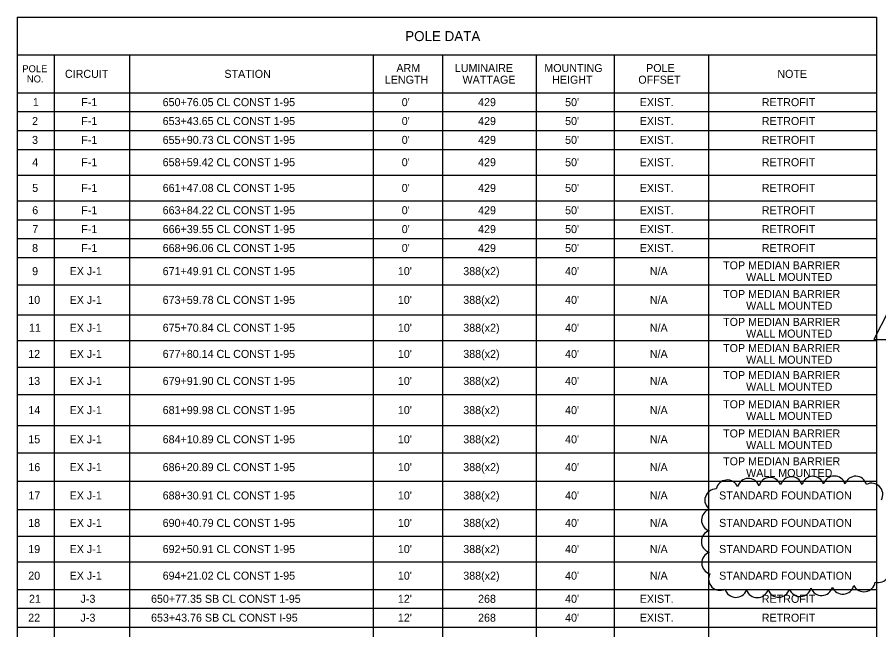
# Model space of a CAD drawing. Extents: x -838.2 to -802.1, y -2200.5 to -2187.7.
# Drawn here: x -817.54 to -810, y -2193.08 to -2187.72 of the extents above; entities that cross this region are included whole.
import ezdxf

# ---------------------------------------------------------------- set-up
doc = ezdxf.new("R2010")
doc.units = 0
for name, color, linetype in [('Cloud_dp', 7, 'Continuous'), ('SumBoxBorder_dp', 7, 'Continuous'), ('SumBoxLines_dp', 7, 'Continuous'), ('SumBoxLinesMin_dp', 7, 'Continuous'), ('TextLabel', 7, 'Continuous')]:
    doc.layers.add(name, color=color, linetype=linetype)

msp = doc.modelspace()

# ---------------------------------------------------------------- linework, layer by layer
at = {"layer": 'Cloud_dp'}
msp.add_lwpolyline([(-809.9202, -2190.2923), (-810.047, -2190.5364), (-809.7935, -2190.5364)], close=True, dxfattribs=at)
for centre, radius, start, end in [((-810.5792, -2191.8323), 0.0985, 18.60955, 163.60955), ((-810.3916, -2191.8298), 0.0985, 17.90326, 162.90326), ((-810.2046, -2191.8315), 0.0986, 16.0749, 161.0749), ((-811.3278, -2191.8641), 0.0985, 23.06971, 168.06971), ((-811.1418, -2191.8504), 0.0985, 20.37871, 165.37871), ((-810.9545, -2191.8424), 0.0985, 19.50674, 164.50674), ((-810.7669, -2191.8366), 0.0985, 19.02787, 164.02787), ((-810.066, -2191.8924), 0.0985, 331.459, 116.459), ((-811.4251, -2191.9423), 0.0985, 89.50987, 234.50987), ((-811.4542, -2192.117), 0.0985, 106.53377, 251.53377), ((-811.4555, -2192.3043), 0.0985, 107.68881, 252.68881), ((-811.4525, -2192.4915), 0.0985, 109.15664, 254.15664), ((-810.0083, -2192.5635), 0.0985, 254.40415, 39.40415), ((-811.3921, -2192.632), 0.0985, 152.35826, 297.35826), ((-810.6905, -2192.6861), 0.0985, 199.81345, 344.81345), ((-810.5031, -2192.6776), 0.0985, 200.35107, 345.35107), ((-810.3163, -2192.6658), 0.0985, 201.87855, 346.87855), ((-810.1322, -2192.644), 0.0985, 206.60481, 351.60481), ((-811.2518, -2192.6935), 0.0985, 195.25606, 340.25606), ((-811.0654, -2192.6962), 0.0985, 198.13107, 343.13107), ((-810.878, -2192.6925), 0.0985, 199.1138, 344.1138)]:
    msp.add_arc(centre, radius, start, end, dxfattribs=at)
at = {"layer": 'SumBoxBorder_dp'}
for p, q in [((-817.5362, -2187.7197), (-810.0212, -2187.7197)), ((-817.5362, -2187.7197), (-817.5362, -2197.0722)), ((-810.0212, -2187.7197), (-810.0212, -2197.0722)), ((-810.0212, -2187.7197), (-810.0212, -2197.0722)), ((-817.5362, -2188.0497), (-810.0212, -2188.0497)), ((-817.5362, -2188.0497), (-810.0212, -2188.0497))]:
    msp.add_line(p, q, dxfattribs=at)
at = {"layer": 'SumBoxLines_dp'}
for p, q in [((-817.2137, -2188.0497), (-817.2137, -2197.0722)), ((-817.2137, -2188.0497), (-817.2137, -2197.0722)), ((-816.5537, -2188.0497), (-816.5537, -2197.0722)), ((-816.5537, -2188.0497), (-816.5537, -2197.0722)), ((-814.4237, -2188.0497), (-814.4237, -2195.0322)), ((-814.4237, -2188.0497), (-814.4237, -2197.0722)), ((-813.8162, -2188.0497), (-813.8162, -2197.0722)), ((-813.8162, -2188.0497), (-813.8162, -2197.0722)), ((-812.9987, -2188.0497), (-812.9987, -2197.0722)), ((-812.9987, -2188.0497), (-812.9987, -2197.0722)), ((-812.3162, -2188.0497), (-812.3162, -2197.0722)), ((-812.3162, -2188.0497), (-812.3162, -2197.0722)), ((-811.4912, -2188.0497), (-811.4912, -2197.0722)), ((-811.4912, -2188.0497), (-811.4912, -2197.0722)), ((-817.5362, -2188.3797), (-810.0212, -2188.3797))]:
    msp.add_line(p, q, dxfattribs=at)
at = {"layer": 'SumBoxLinesMin_dp'}
for p, q in [((-817.5362, -2188.3797), (-810.0212, -2188.3797)), ((-817.5362, -2188.5447), (-810.0212, -2188.5447)), ((-817.5362, -2188.5447), (-810.0212, -2188.5447)), ((-817.5362, -2188.7097), (-810.0212, -2188.7097)), ((-817.5362, -2188.7097), (-810.0212, -2188.7097)), ((-817.5362, -2188.8747), (-810.0212, -2188.8747)), ((-817.5362, -2188.8747), (-810.0212, -2188.8747)), ((-817.5362, -2189.0997), (-810.0212, -2189.0997)), ((-817.5362, -2189.0997), (-810.0212, -2189.0997)), ((-817.5362, -2189.3247), (-810.0212, -2189.3247)), ((-817.5362, -2189.3247), (-810.0212, -2189.3247)), ((-817.5362, -2189.4897), (-810.0212, -2189.4897)), ((-817.5362, -2189.4897), (-810.0212, -2189.4897)), ((-817.5362, -2189.6547), (-810.0212, -2189.6547)), ((-817.5362, -2189.6547), (-810.0212, -2189.6547)), ((-817.5362, -2189.8197), (-810.0212, -2189.8197)), ((-817.5362, -2189.8197), (-810.0212, -2189.8197)), ((-817.5362, -2190.0597), (-810.0212, -2190.0597)), ((-817.5362, -2190.0597), (-810.0212, -2190.0597)), ((-817.5362, -2190.3222), (-810.0212, -2190.3222)), ((-817.5362, -2190.3222), (-810.0212, -2190.3222)), ((-817.5362, -2190.5472), (-810.0212, -2190.5472)), ((-817.5362, -2190.5472), (-810.0212, -2190.5472)), ((-817.5362, -2190.7797), (-810.0212, -2190.7797)), ((-817.5362, -2190.7797), (-810.0212, -2190.7797)), ((-817.5362, -2191.0197), (-810.0212, -2191.0197)), ((-817.5362, -2191.0197), (-810.0212, -2191.0197)), ((-817.5362, -2191.2897), (-810.0212, -2191.2897)), ((-817.5362, -2191.2897), (-810.0212, -2191.2897)), ((-817.5362, -2191.5297), (-810.0212, -2191.5297)), ((-817.5362, -2191.5297), (-810.0212, -2191.5297)), ((-817.5362, -2191.7772), (-810.0212, -2191.7772)), ((-817.5362, -2191.7772), (-810.0212, -2191.7772)), ((-817.5362, -2192.0247), (-810.0212, -2192.0247)), ((-817.5362, -2192.0247), (-810.0212, -2192.0247)), ((-817.5362, -2192.2572), (-810.0212, -2192.2572)), ((-817.5362, -2192.2572), (-810.0212, -2192.2572)), ((-817.5362, -2192.4822), (-810.0212, -2192.4822)), ((-817.5362, -2192.4822), (-810.0212, -2192.4822)), ((-817.5362, -2192.7222), (-810.0212, -2192.7222)), ((-817.5362, -2192.7222), (-810.0212, -2192.7222)), ((-817.5362, -2192.8872), (-810.0212, -2192.8872)), ((-817.5362, -2192.8872), (-810.0212, -2192.8872)), ((-817.5362, -2193.0522), (-810.0212, -2193.0522)), ((-817.5362, -2193.0522), (-810.0212, -2193.0522))]:
    msp.add_line(p, q, dxfattribs=at)

# ---------------------------------------------------------------- texts
at = {"layer": 'TextLabel'}
for s, height, p in [('POLE DATA', 0.0875, (-814.1436, -2187.9284)), ('POLE', 0.06125, (-817.4916, -2188.2007)), ('CIRCUIT', 0.07, (-817.119, -2188.2497)), ('STATION', 0.07, (-815.7245, -2188.2497)), ('ARM', 0.07, (-814.2204, -2188.1987)), ('LUMINAIRE', 0.07, (-813.7101, -2188.1987)), ('MOUNTING', 0.07, (-812.9271, -2188.1987)), ('POLE', 0.07, (-812.037, -2188.1987)), ('NOTE', 0.07, (-810.8895, -2188.2497)), ('NO.', 0.06125, (-817.4516, -2188.2899)), ('LENGTH', 0.07, (-814.3219, -2188.3007)), ('WATTAGE', 0.07, (-813.6424, -2188.3007)), ('HEIGHT', 0.07, (-812.8589, -2188.3007)), ('OFFSET', 0.07, (-812.1052, -2188.3007)), ('1', 0.07, (-817.3996, -2188.4972)), ('F-1', 0.07, (-816.9761, -2188.4972)), ('650+76.05 CL CONST 1-95', 0.07, (-816.2645, -2188.4972)), ("0'", 0.07, (-814.174, -2188.4972)), ('429', 0.07, (-813.5062, -2188.4972)), ("50'", 0.07, (-812.7454, -2188.4972)), ('EXIST.', 0.07, (-812.093, -2188.4972)), ('RETROFIT', 0.07, (-811.0254, -2188.4972)), ('2', 0.07, (-817.4063, -2188.6622)), ('F-1', 0.07, (-816.9761, -2188.6622)), ('653+43.65 CL CONST 1-95', 0.07, (-816.2645, -2188.6622)), ("0'", 0.07, (-814.174, -2188.6622)), ('429', 0.07, (-813.5062, -2188.6622)), ("50'", 0.07, (-812.7454, -2188.6622)), ('EXIST.', 0.07, (-812.093, -2188.6622)), ('RETROFIT', 0.07, (-811.0254, -2188.6622)), ('3', 0.07, (-817.4064, -2188.8272)), ('F-1', 0.07, (-816.9761, -2188.8272)), ('655+90.73 CL CONST 1-95', 0.07, (-816.2645, -2188.8272)), ("0'", 0.07, (-814.174, -2188.8272)), ('429', 0.07, (-813.5062, -2188.8272)), ("50'", 0.07, (-812.7454, -2188.8272)), ('EXIST.', 0.07, (-812.093, -2188.8272)), ('RETROFIT', 0.07, (-811.0254, -2188.8272)), ('4', 0.07, (-817.405, -2189.0222)), ('F-1', 0.07, (-816.9761, -2189.0222)), ('658+59.42 CL CONST 1-95', 0.07, (-816.2645, -2189.0222)), ("0'", 0.07, (-814.174, -2189.0222)), ('429', 0.07, (-813.5062, -2189.0222)), ("50'", 0.07, (-812.7454, -2189.0222)), ('EXIST.', 0.07, (-812.093, -2189.0222)), ('RETROFIT', 0.07, (-811.0254, -2189.0222)), ('5', 0.07, (-817.4055, -2189.2472)), ('F-1', 0.07, (-816.9761, -2189.2472)), ('661+47.08 CL CONST 1-95', 0.07, (-816.2645, -2189.2472)), ("0'", 0.07, (-814.174, -2189.2472)), ('429', 0.07, (-813.5062, -2189.2472)), ("50'", 0.07, (-812.7454, -2189.2472)), ('EXIST.', 0.07, (-812.093, -2189.2472)), ('RETROFIT', 0.07, (-811.0254, -2189.2472)), ('6', 0.07, (-817.405, -2189.4422)), ('F-1', 0.07, (-816.9761, -2189.4422)), ('663+84.22 CL CONST 1-95', 0.07, (-816.2645, -2189.4422)), ("0'", 0.07, (-814.174, -2189.4422)), ('429', 0.07, (-813.5062, -2189.4422)), ("50'", 0.07, (-812.7454, -2189.4422)), ('EXIST.', 0.07, (-812.093, -2189.4422)), ('RETROFIT', 0.07, (-811.0254, -2189.4422)), ('7', 0.07, (-817.4043, -2189.6072)), ('F-1', 0.07, (-816.9761, -2189.6072)), ('666+39.55 CL CONST 1-95', 0.07, (-816.2645, -2189.6072)), ("0'", 0.07, (-814.174, -2189.6072)), ('429', 0.07, (-813.5062, -2189.6072)), ("50'", 0.07, (-812.7454, -2189.6072)), ('EXIST.', 0.07, (-812.093, -2189.6072)), ('RETROFIT', 0.07, (-811.0254, -2189.6072)), ('8', 0.07, (-817.4061, -2189.7722)), ('F-1', 0.07, (-816.9761, -2189.7722)), ('668+96.06 CL CONST 1-95', 0.07, (-816.2645, -2189.7722)), ("0'", 0.07, (-814.174, -2189.7722)), ('429', 0.07, (-813.5062, -2189.7722)), ("50'", 0.07, (-812.7454, -2189.7722)), ('EXIST.', 0.07, (-812.093, -2189.7722)), ('RETROFIT', 0.07, (-811.0254, -2189.7722)), ('TOP MEDIAN BARRIER', 0.07, (-811.3638, -2189.9237)), ('9', 0.07, (-817.406, -2189.9747)), ('EX J-1', 0.07, (-817.0777, -2189.9747)), ('671+49.91 CL CONST 1-95', 0.07, (-816.2645, -2189.9747)), ("10'", 0.07, (-814.2079, -2189.9747)), ('388(x2)', 0.07, (-813.6359, -2189.9747)), ("40'", 0.07, (-812.7454, -2189.9747)), ('N/A', 0.07, (-812.0043, -2189.9747)), ('WALL MOUNTED', 0.07, (-811.1625, -2190.0257)), ('10', 0.07, (-817.4396, -2190.2259)), ('673+59.78 CL CONST 1-95', 0.07, (-816.2645, -2190.2259)), ("10'", 0.07, (-814.2079, -2190.2259)), ('388(x2)', 0.07, (-813.6359, -2190.2259)), ("40'", 0.07, (-812.7454, -2190.2259)), ('N/A', 0.07, (-812.0043, -2190.2259)), ('TOP MEDIAN BARRIER', 0.07, (-811.3638, -2190.1749)), ('EX J-1', 0.07, (-817.0777, -2190.2259)), ('WALL MOUNTED', 0.07, (-811.1625, -2190.2769)), ('TOP MEDIAN BARRIER', 0.07, (-811.3638, -2190.4187)), ('11', 0.07, (-817.4335, -2190.4697)), ('EX J-1', 0.07, (-817.0777, -2190.4697)), ('675+70.84 CL CONST 1-95', 0.07, (-816.2645, -2190.4697)), ("10'", 0.07, (-814.2079, -2190.4697)), ('388(x2)', 0.07, (-813.6359, -2190.4697)), ("40'", 0.07, (-812.7454, -2190.4697)), ('N/A', 0.07, (-812.0043, -2190.4697)), ('WALL MOUNTED', 0.07, (-811.1625, -2190.5207)), ('TOP MEDIAN BARRIER', 0.07, (-811.3638, -2190.6474)), ('12', 0.07, (-817.4402, -2190.6984)), ('EX J-1', 0.07, (-817.0777, -2190.6984)), ('677+80.14 CL CONST 1-95', 0.07, (-816.2645, -2190.6984)), ("10'", 0.07, (-814.2079, -2190.6984)), ('388(x2)', 0.07, (-813.6359, -2190.6984)), ("40'", 0.07, (-812.7454, -2190.6984)), ('N/A', 0.07, (-812.0043, -2190.6984)), ('WALL MOUNTED', 0.07, (-811.1625, -2190.7494)), ('TOP MEDIAN BARRIER', 0.07, (-811.3638, -2190.8837)), ('13', 0.07, (-817.4403, -2190.9347)), ('EX J-1', 0.07, (-817.0777, -2190.9347)), ('679+91.90 CL CONST 1-95', 0.07, (-816.2645, -2190.9347)), ("10'", 0.07, (-814.2079, -2190.9347)), ('388(x2)', 0.07, (-813.6359, -2190.9347)), ("40'", 0.07, (-812.7454, -2190.9347)), ('N/A', 0.07, (-812.0043, -2190.9347)), ('WALL MOUNTED', 0.07, (-811.1625, -2190.9857)), ('14', 0.07, (-817.4389, -2191.1897)), ('EX J-1', 0.07, (-817.0777, -2191.1897)), ('681+99.98 CL CONST 1-95', 0.07, (-816.2645, -2191.1897)), ("10'", 0.07, (-814.2079, -2191.1897)), ('388(x2)', 0.07, (-813.6359, -2191.1897)), ("40'", 0.07, (-812.7454, -2191.1897)), ('N/A', 0.07, (-812.0043, -2191.1897)), ('TOP MEDIAN BARRIER', 0.07, (-811.3638, -2191.1387)), ('WALL MOUNTED', 0.07, (-811.1625, -2191.2407)), ('TOP MEDIAN BARRIER', 0.07, (-811.3638, -2191.3937)), ('15', 0.07, (-817.4393, -2191.4447)), ('EX J-1', 0.07, (-817.0777, -2191.4447)), ('684+10.89 CL CONST 1-95', 0.07, (-816.2645, -2191.4447)), ("10'", 0.07, (-814.2079, -2191.4447)), ('388(x2)', 0.07, (-813.6359, -2191.4447)), ("40'", 0.07, (-812.7454, -2191.4447)), ('N/A', 0.07, (-812.0043, -2191.4447)), ('WALL MOUNTED', 0.07, (-811.1625, -2191.4957)), ('TOP MEDIAN BARRIER', 0.07, (-811.3638, -2191.6374)), ('16', 0.07, (-817.4388, -2191.6884)), ('EX J-1', 0.07, (-817.0777, -2191.6884)), ('686+20.89 CL CONST 1-95', 0.07, (-816.2645, -2191.6884)), ("10'", 0.07, (-814.2079, -2191.6884)), ('388(x2)', 0.07, (-813.6359, -2191.6884)), ("40'", 0.07, (-812.7454, -2191.6884)), ('N/A', 0.07, (-812.0043, -2191.6884)), ('WALL MOUNTED', 0.07, (-811.1625, -2191.7394)), ('17', 0.07, (-817.4382, -2191.9359)), ('EX J-1', 0.07, (-817.0777, -2191.9359)), ('688+30.91 CL CONST 1-95', 0.07, (-816.2645, -2191.9359)), ("10'", 0.07, (-814.2079, -2191.9359)), ('388(x2)', 0.07, (-813.6359, -2191.9359)), ("40'", 0.07, (-812.7454, -2191.9359)), ('N/A', 0.07, (-812.0043, -2191.9359)), ('STANDARD FOUNDATION', 0.07, (-811.3986, -2191.9359)), ('18', 0.07, (-817.44, -2192.1759)), ('EX J-1', 0.07, (-817.0777, -2192.1759)), ('690+40.79 CL CONST 1-95', 0.07, (-816.2645, -2192.1759)), ("10'", 0.07, (-814.2079, -2192.1759)), ('388(x2)', 0.07, (-813.6359, -2192.1759)), ("40'", 0.07, (-812.7454, -2192.1759)), ('N/A', 0.07, (-812.0043, -2192.1759)), ('STANDARD FOUNDATION', 0.07, (-811.3986, -2192.1759)), ('19', 0.07, (-817.4398, -2192.4047)), ('EX J-1', 0.07, (-817.0777, -2192.4047)), ('692+50.91 CL CONST 1-95', 0.07, (-816.2645, -2192.4047)), ("10'", 0.07, (-814.2079, -2192.4047)), ('388(x2)', 0.07, (-813.6359, -2192.4047)), ("40'", 0.07, (-812.7454, -2192.4047)), ('N/A', 0.07, (-812.0043, -2192.4047)), ('STANDARD FOUNDATION', 0.07, (-811.3986, -2192.4047)), ('388(x2)', 0.07, (-813.6359, -2192.6372)), ('N/A', 0.07, (-812.0043, -2192.6372)), ('20', 0.07, (-817.4396, -2192.6372)), ('EX J-1', 0.07, (-817.0777, -2192.6372)), ('694+21.02 CL CONST 1-95', 0.07, (-816.2645, -2192.6372)), ("10'", 0.07, (-814.2079, -2192.6372)), ("40'", 0.07, (-812.7454, -2192.6372)), ('STANDARD FOUNDATION', 0.07, (-811.3986, -2192.6372)), ('21', 0.07, (-817.4335, -2192.8397)), ('J-3', 0.07, (-816.9829, -2192.8397)), ('650+77.35 SB CL CONST 1-95', 0.07, (-816.3661, -2192.8397)), ("12'", 0.07, (-814.2079, -2192.8397)), ('268', 0.07, (-813.5064, -2192.8397)), ("40'", 0.07, (-812.7454, -2192.8397)), ('EXIST.', 0.07, (-812.093, -2192.8397)), ('RETROFIT', 0.07, (-811.0254, -2192.8397)), ('22', 0.07, (-817.4402, -2193.0047)), ('J-3', 0.07, (-816.9829, -2193.0047)), ('653+43.76 SB CL CONST I-95', 0.07, (-816.3661, -2193.0047)), ("12'", 0.07, (-814.2079, -2193.0047)), ('268', 0.07, (-813.5064, -2193.0047)), ("40'", 0.07, (-812.7454, -2193.0047)), ('EXIST.', 0.07, (-812.093, -2193.0047)), ('RETROFIT', 0.07, (-811.0254, -2193.0047))]:
    msp.add_text(s, height=height, dxfattribs=at).set_placement(p)

doc.saveas('drawing.dxf')
